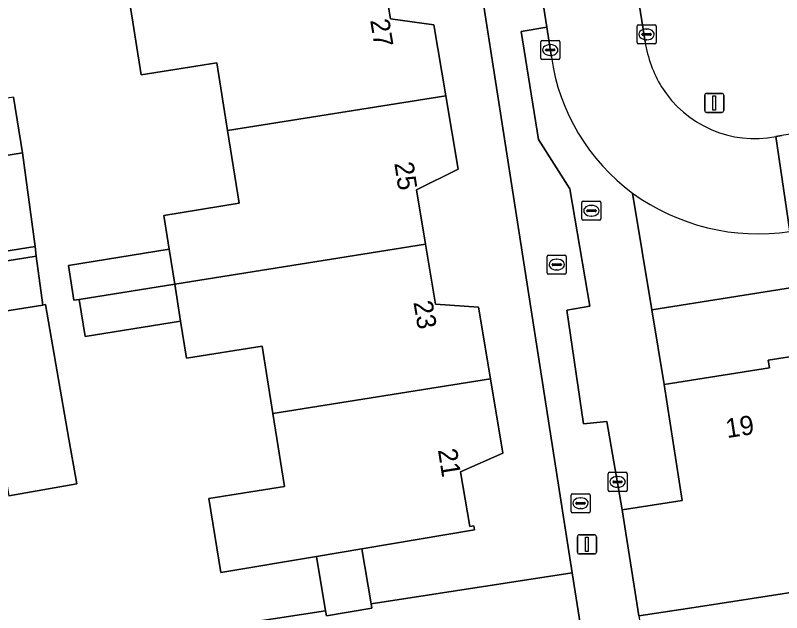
# Model space of a CAD drawing. Extents: x 160077 to 160948, y 386481 to 387498.
# Drawn here: x 160504.27 to 160544.36, y 387057.29 to 387088.51 of the extents above; entities that cross this region are included whole.
import ezdxf

# ---------------------------------------------------------------- set-up
doc = ezdxf.new("R2010")
doc.units = 0
for name, color, linetype in [('IMGEO_Brandkraan', 7, 'Continuous'), ('IMGEO_Erf', 7, 'Continuous'), ('IMGEO_Kolk', 7, 'Continuous'), ('IMGEO_Lichtmast', 7, 'Continuous'), ('IMGEO_Pand', 7, 'Continuous'), ('IMGEO_Pand_nummerreeks', 7, 'Continuous'), ('IMGEO_Rijbaan_lokaal_open', 7, 'Continuous'), ('IMGEO_Rioolput', 7, 'Continuous'), ('IMGEO_Voetpad_open', 7, 'Continuous')]:
    doc.layers.add(name, color=color, linetype=linetype)

msp = doc.modelspace()

# ---------------------------------------------------------------- linework, layer by layer
at = {"layer": 'IMGEO_Brandkraan'}
for p, q in [((160532.165, 387075.985), (160533.017, 387075.985)), ((160532.09, 387075.059), (160532.09, 387075.911)), ((160532.578, 387075.765), (160532.603, 387075.765)), ((160533.091, 387075.911), (160533.091, 387075.059)), ((160532.349, 387075.479), (160532.349, 387075.491)), ((160532.787, 387075.442), (160532.389, 387075.442)), ((160532.392, 387075.528), (160532.79, 387075.528)), ((160532.601, 387075.205), (160532.576, 387075.205)), ((160532.833, 387075.491), (160532.833, 387075.479)), ((160533.017, 387074.985), (160532.165, 387074.985))]:
    msp.add_line(p, q, dxfattribs=at)
for points in [[(160532.165, 387075.985), (160533.017, 387075.985)], [(160532.09, 387075.059), (160532.09, 387075.911)], [(160533.091, 387075.911), (160533.091, 387075.059)], [(160533.017, 387074.985), (160532.165, 387074.985)]]:
    msp.add_lwpolyline(points, dxfattribs=at)
for centre, radius, start, end in [((160532.167, 387075.909), 0.0765, 91.552, 178.448), ((160532.167, 387075.909), 0.0765, 91.552, 178.448), ((160533.015, 387075.909), 0.0765, 1.552, 88.448), ((160533.015, 387075.909), 0.0765, 1.552, 88.448), ((160532.389, 387075.488), 0.0403, 85.8775, 175.7526), ((160532.386, 387075.478), 0.0366, 178.938, 274.7102), ((160532.79, 387075.485), 0.043, 264.8664, 352.4533), ((160532.794, 387075.49), 0.0386, 1.7309, 96.639), ((160532.167, 387075.061), 0.0765, 181.552, 268.448), ((160532.167, 387075.061), 0.0765, 181.552, 268.448), ((160533.015, 387075.061), 0.0765, 271.552, 358.448), ((160533.015, 387075.061), 0.0765, 271.552, 358.448)]:
    msp.add_arc(centre, radius, start, end, dxfattribs=at)
for centre, major_axis, ratio, start_param, end_param in [((160532.577, 387075.485), (-0.387, 0.002), 0.722429, 4.712389, 7.853982), ((160532.602, 387075.485), (-0.39, 0.002), 0.717154, 1.570796, 4.712389)]:
    msp.add_ellipse(centre, major_axis=major_axis, ratio=ratio, start_param=start_param, end_param=end_param, dxfattribs=at)
at = {"layer": 'IMGEO_Erf'}
for points in [[(160523.386, 387091.347), (160523.894, 387088.324), (160526.165, 387088.024), (160526.789, 387084.31), (160527.434, 387080.472), (160525.253, 387079.396), (160525.729, 387076.56), (160526.258, 387073.412), (160528.494, 387073.265), (160529.123, 387069.522), (160529.777, 387065.633), (160527.558, 387064.656), (160528.038, 387061.796), (160528.256, 387061.832), (160528.292, 387061.615), (160522.396, 387060.624), (160522.879, 387057.753), (160533.389, 387059.367), (160524.807, 387114.481)], [(160513.761, 387056.353), (160520.499, 387057.388), (160520.022, 387060.225), (160515.019, 387059.383), (160514.4, 387063.252), (160518.349, 387063.884), (160517.738, 387067.704), (160517.175, 387071.228), (160513.228, 387070.597), (160512.92, 387072.526), (160507.922, 387071.727), (160507.612, 387073.666), (160507.338, 387073.622), (160507.047, 387075.445), (160512.318, 387076.288), (160512.035, 387078.06), (160515.984, 387078.692), (160515.377, 387082.487), (160514.81, 387086.036), (160510.863, 387085.404), (160510.248, 387089.249)], [(160624.64, 387086.938), (160537.562, 387073.116), (160538.202, 387069.219), (160543.71, 387070.083), (160543.647, 387070.489), (160545.319, 387070.751)], [(160504.177, 387084.241), (160504.641, 387081.322), (160505.303, 387076.429), (160505.37, 387075.934), (160505.717, 387073.37), (160505.847, 387073.391), (160507.076, 387066.352), (160507.483, 387064.019), (160503.937, 387063.399)], [(160547.186, 387058.717), (160540.007, 387057.603), (160536.884, 387057.118), (160537.023, 387056.231), (160538.348, 387047.784), (160601.152, 387057.778)]]:
    msp.add_lwpolyline(points, dxfattribs=at)
at = {"layer": 'IMGEO_Kolk'}
for p, q in [((160536.864, 387088.02), (160537.716, 387088.02)), ((160536.789, 387087.094), (160536.789, 387087.946)), ((160537.277, 387087.8), (160537.302, 387087.8)), ((160537.79, 387087.946), (160537.79, 387087.094)), ((160537.048, 387087.514), (160537.048, 387087.526)), ((160537.486, 387087.477), (160537.088, 387087.477)), ((160537.091, 387087.563), (160537.489, 387087.563)), ((160537.3, 387087.24), (160537.275, 387087.24)), ((160537.532, 387087.526), (160537.532, 387087.514)), ((160531.752, 387086.276), (160531.752, 387087.128)), ((160531.827, 387087.202), (160532.679, 387087.202)), ((160532.24, 387086.982), (160532.265, 387086.982)), ((160532.753, 387087.128), (160532.753, 387086.276)), ((160537.716, 387087.02), (160536.864, 387087.02)), ((160532.011, 387086.696), (160532.011, 387086.708)), ((160532.449, 387086.659), (160532.051, 387086.659)), ((160532.054, 387086.745), (160532.452, 387086.745)), ((160532.263, 387086.422), (160532.238, 387086.422)), ((160532.495, 387086.708), (160532.495, 387086.696)), ((160532.679, 387086.202), (160531.827, 387086.202)), ((160535.273, 387063.701), (160535.273, 387064.553)), ((160535.348, 387064.627), (160536.2, 387064.627)), ((160535.761, 387064.407), (160535.786, 387064.407)), ((160536.274, 387064.553), (160536.274, 387063.701)), ((160535.532, 387064.121), (160535.532, 387064.133)), ((160535.97, 387064.084), (160535.572, 387064.084)), ((160535.575, 387064.17), (160535.973, 387064.17)), ((160536.016, 387064.133), (160536.016, 387064.121)), ((160536.2, 387063.627), (160535.348, 387063.627)), ((160535.784, 387063.847), (160535.759, 387063.847))]:
    msp.add_line(p, q, dxfattribs=at)
for points in [[(160536.864, 387088.02), (160537.716, 387088.02)], [(160536.789, 387087.094), (160536.789, 387087.946)], [(160537.79, 387087.946), (160537.79, 387087.094)], [(160531.752, 387086.276), (160531.752, 387087.128)], [(160531.827, 387087.202), (160532.679, 387087.202)], [(160532.753, 387087.128), (160532.753, 387086.276)], [(160537.716, 387087.02), (160536.864, 387087.02)], [(160532.679, 387086.202), (160531.827, 387086.202)], [(160535.273, 387063.701), (160535.273, 387064.553)], [(160535.348, 387064.627), (160536.2, 387064.627)], [(160536.274, 387064.553), (160536.274, 387063.701)], [(160536.2, 387063.627), (160535.348, 387063.627)]]:
    msp.add_lwpolyline(points, dxfattribs=at)
for centre, radius, start, end in [((160536.866, 387087.944), 0.0765, 91.552, 178.448), ((160536.866, 387087.944), 0.0765, 91.552, 178.448), ((160537.714, 387087.944), 0.0765, 1.552, 88.448), ((160537.714, 387087.944), 0.0765, 1.552, 88.448), ((160537.088, 387087.523), 0.0403, 85.8775, 175.7526), ((160537.085, 387087.513), 0.0366, 178.938, 274.7102), ((160537.489, 387087.52), 0.043, 264.8664, 352.4533), ((160537.493, 387087.525), 0.0386, 1.7309, 96.639), ((160531.829, 387087.126), 0.0765, 91.552, 178.448), ((160531.829, 387087.126), 0.0765, 91.552, 178.448), ((160532.677, 387087.126), 0.0765, 1.552, 88.448), ((160532.677, 387087.126), 0.0765, 1.552, 88.448), ((160536.866, 387087.096), 0.0765, 181.552, 268.448), ((160536.866, 387087.096), 0.0765, 181.552, 268.448), ((160537.714, 387087.096), 0.0765, 271.552, 358.448), ((160537.714, 387087.096), 0.0765, 271.552, 358.448), ((160532.051, 387086.705), 0.0403, 85.8775, 175.7526), ((160532.048, 387086.695), 0.0366, 178.938, 274.7102), ((160532.452, 387086.702), 0.043, 264.8664, 352.4533), ((160532.456, 387086.707), 0.0386, 1.7309, 96.639), ((160531.829, 387086.278), 0.0765, 181.552, 268.448), ((160531.829, 387086.278), 0.0765, 181.552, 268.448), ((160532.677, 387086.278), 0.0765, 271.552, 358.448), ((160532.677, 387086.278), 0.0765, 271.552, 358.448), ((160535.35, 387064.551), 0.0765, 91.552, 178.448), ((160535.35, 387064.551), 0.0765, 91.552, 178.448), ((160536.198, 387064.551), 0.0765, 1.552, 88.448), ((160536.198, 387064.551), 0.0765, 1.552, 88.448), ((160535.572, 387064.13), 0.0403, 85.8775, 175.7526), ((160535.569, 387064.12), 0.0366, 178.938, 274.7102), ((160535.973, 387064.127), 0.043, 264.8664, 352.4533), ((160535.977, 387064.132), 0.0386, 1.7309, 96.639), ((160535.35, 387063.703), 0.0765, 181.552, 268.448), ((160535.35, 387063.703), 0.0765, 181.552, 268.448), ((160536.198, 387063.703), 0.0765, 271.552, 358.448), ((160536.198, 387063.703), 0.0765, 271.552, 358.448)]:
    msp.add_arc(centre, radius, start, end, dxfattribs=at)
for centre, major_axis, ratio, start_param, end_param in [((160537.276, 387087.52), (-0.387, 0.002), 0.722429, 4.712389, 7.853982), ((160537.301, 387087.52), (-0.39, 0.002), 0.717154, 1.570796, 4.712389), ((160532.239, 387086.702), (-0.387, 0.002), 0.722429, 4.712389, 7.853982), ((160532.264, 387086.702), (-0.39, 0.002), 0.717154, 1.570796, 4.712389), ((160535.76, 387064.127), (-0.387, 0.002), 0.722429, 4.712389, 7.853982), ((160535.785, 387064.127), (-0.39, 0.002), 0.717154, 1.570796, 4.712389)]:
    msp.add_ellipse(centre, major_axis=major_axis, ratio=ratio, start_param=start_param, end_param=end_param, dxfattribs=at)
at = {"layer": 'IMGEO_Lichtmast'}
for p, q in [((160540.432, 387084.437), (160541.222, 387084.437)), ((160541.222, 387084.437), (160540.432, 387084.437)), ((160540.332, 387083.537), (160540.332, 387084.337)), ((160540.332, 387084.337), (160540.332, 387083.537)), ((160541.322, 387084.337), (160541.322, 387083.537)), ((160541.322, 387083.537), (160541.322, 387084.337)), ((160541.222, 387083.437), (160540.432, 387083.437)), ((160540.432, 387083.437), (160541.222, 387083.437)), ((160533.673, 387060.458), (160533.673, 387061.258)), ((160533.673, 387061.258), (160533.673, 387060.458)), ((160533.773, 387061.358), (160534.563, 387061.358)), ((160534.563, 387061.358), (160533.773, 387061.358)), ((160534.663, 387061.258), (160534.663, 387060.458)), ((160534.663, 387060.458), (160534.663, 387061.258)), ((160534.563, 387060.358), (160533.773, 387060.358)), ((160533.773, 387060.358), (160534.563, 387060.358))]:
    msp.add_line(p, q, dxfattribs=at)
for points in [[(160540.752, 387084.312), (160540.902, 387084.312), (160540.902, 387083.562), (160540.752, 387083.562), (160540.752, 387084.312)], [(160534.093, 387061.233), (160534.243, 387061.233), (160534.243, 387060.483), (160534.093, 387060.483), (160534.093, 387061.233)]]:
    msp.add_lwpolyline(points, dxfattribs=at)
for centre, start, end in [((160540.432, 387084.337), 90, 180), ((160540.432, 387084.337), 90, 180), ((160541.222, 387084.337), 0, 90), ((160541.222, 387084.337), 360, 90), ((160540.432, 387083.537), 180, 270), ((160540.432, 387083.537), 180, 270), ((160541.222, 387083.537), 270, 0), ((160541.222, 387083.537), 270, 0), ((160533.773, 387061.258), 90, 180), ((160533.773, 387061.258), 90, 180), ((160534.563, 387061.258), 0, 90), ((160534.563, 387061.258), 360, 90), ((160533.773, 387060.458), 180, 270), ((160533.773, 387060.458), 180, 270), ((160534.563, 387060.458), 270, 0), ((160534.563, 387060.458), 270, 0)]:
    msp.add_arc(centre, 0.1, start, end, dxfattribs=at)
at = {"layer": 'IMGEO_Pand'}
for points in [[(160526.789, 387084.31), (160526.165, 387088.024), (160523.894, 387088.324), (160523.386, 387091.347), (160510.248, 387089.249), (160510.863, 387085.404), (160514.81, 387086.036), (160515.377, 387082.487)], [(160500, 387080.586), (160504.641, 387081.322), (160504.177, 387084.241), (160498.21, 387083.295), (160498.595, 387080.868), (160498.673, 387080.375)], [(160525.253, 387079.396), (160527.434, 387080.472), (160526.789, 387084.31), (160515.377, 387082.487), (160515.984, 387078.692), (160512.035, 387078.06), (160512.318, 387076.288), (160512.61, 387074.464), (160525.729, 387076.56)], [(160528.494, 387073.265), (160526.258, 387073.412), (160525.729, 387076.56), (160512.61, 387074.464), (160512.92, 387072.526), (160513.228, 387070.597), (160517.175, 387071.228), (160517.738, 387067.704), (160529.123, 387069.522)], [(160512.318, 387076.288), (160507.047, 387075.445), (160507.338, 387073.622), (160507.612, 387073.666), (160512.61, 387074.464)], [(160512.61, 387074.464), (160507.612, 387073.666), (160507.922, 387071.727), (160512.92, 387072.526)], [(160505.847, 387073.391), (160505.717, 387073.37), (160502.382, 387072.837), (160500, 387072.464), (160499.63, 387072.405), (160500.772, 387065.316), (160503.529, 387065.735), (160503.937, 387063.399), (160507.483, 387064.019), (160507.076, 387066.352)], [(160545.319, 387070.751), (160543.647, 387070.489), (160543.71, 387070.083), (160538.202, 387069.219), (160539.152, 387063.158), (160536.014, 387062.666), (160536.884, 387057.118), (160540.007, 387057.603), (160547.186, 387058.717), (160546.762, 387061.449)], [(160527.558, 387064.656), (160529.777, 387065.633), (160529.123, 387069.522), (160517.738, 387067.704), (160518.349, 387063.884), (160514.4, 387063.252), (160515.019, 387059.383), (160520.022, 387060.225), (160522.396, 387060.624), (160528.292, 387061.615), (160528.256, 387061.832), (160528.038, 387061.796)], [(160522.396, 387060.624), (160520.022, 387060.225), (160520.499, 387057.388), (160520.542, 387057.133), (160522.916, 387057.532), (160522.879, 387057.753)]]:
    msp.add_lwpolyline(points, close=True, dxfattribs=at)
at = {"layer": 'IMGEO_Rijbaan_lokaal_open'}
for points in [[(160524.318, 387136.787), (160526.43, 387124.048), (160527.09, 387119.812), (160527.668, 387116.105), (160527.923, 387114.471), (160528.364, 387111.64), (160529.664, 387103.302), (160530.562, 387097.546), (160532.066, 387087.893), (160532.31, 387086.331)], [(160537.214, 387087.127), (160532.759, 387115.209)], [(160630.749, 387096.134), (160617.421, 387094.065), (160617.383, 387094.044), (160613.925, 387093.125), (160613.306, 387093.026), (160589.61, 387089.37), (160584.446, 387088.555), (160544.358, 387082.226), (160544.051, 387082.178), (160544.782, 387077.213), (160574.18, 387081.761), (160607.245, 387087.027), (160611.413, 387087.739)], [(160544.782, 387077.213), (160544.051, 387082.178)]]:
    msp.add_lwpolyline(points, dxfattribs=at)
msp.add_lwpolyline([(160483.354, 387072.919), (160490.26, 387074.023), (160496.256, 387074.982), (160500, 387075.581), (160501.689, 387075.851), (160505.303, 387076.429), (160504.641, 387081.322), (160500, 387080.586), (160498.673, 387080.375), (160490.963, 387079.169), (160478.664, 387077.241), (160470.935, 387076.063), (160437.327, 387070.778), (160435.139, 387070.405), (160436.002, 387065.438), (160442.001, 387066.434), (160448.787, 387067.486), (160458.501, 387068.993), (160464.952, 387069.994), (160468.583, 387070.557), (160473.836, 387071.397), (160474.64, 387071.526)], close=True, dxfattribs=at)
for centre, radius, start, end in [((160543.916, 387088.24), 6.794, 189.4247, 210.7093), ((160542.894, 387087.836), 10.691, 188.0931, 233.6659), ((160542.954, 387087.833), 5.761, 212.1234, 280.9805), ((160543.131, 387088.276), 11.185, 234.0236, 278.4884)]:
    msp.add_arc(centre, radius, start, end, dxfattribs=at)
at = {"layer": 'IMGEO_Rioolput'}
for p, q in [((160533.977, 387078.801), (160534.829, 387078.801)), ((160533.902, 387077.875), (160533.902, 387078.727)), ((160534.39, 387078.581), (160534.415, 387078.581)), ((160534.903, 387078.727), (160534.903, 387077.875)), ((160534.161, 387078.295), (160534.161, 387078.307)), ((160534.599, 387078.258), (160534.201, 387078.258)), ((160534.204, 387078.344), (160534.602, 387078.344)), ((160534.413, 387078.021), (160534.388, 387078.021)), ((160534.645, 387078.307), (160534.645, 387078.295)), ((160534.829, 387077.801), (160533.977, 387077.801)), ((160533.337, 387062.584), (160533.337, 387063.436)), ((160533.412, 387063.51), (160534.264, 387063.51)), ((160533.825, 387063.29), (160533.85, 387063.29)), ((160534.338, 387063.436), (160534.338, 387062.584)), ((160533.596, 387063.004), (160533.596, 387063.016)), ((160534.034, 387062.967), (160533.636, 387062.967)), ((160533.639, 387063.053), (160534.037, 387063.053)), ((160534.08, 387063.016), (160534.08, 387063.004)), ((160534.264, 387062.51), (160533.412, 387062.51)), ((160533.848, 387062.73), (160533.823, 387062.73))]:
    msp.add_line(p, q, dxfattribs=at)
for points in [[(160533.977, 387078.801), (160534.829, 387078.801)], [(160533.902, 387077.875), (160533.902, 387078.727)], [(160534.903, 387078.727), (160534.903, 387077.875)], [(160534.829, 387077.801), (160533.977, 387077.801)], [(160533.337, 387062.584), (160533.337, 387063.436)], [(160533.412, 387063.51), (160534.264, 387063.51)], [(160534.338, 387063.436), (160534.338, 387062.584)], [(160534.264, 387062.51), (160533.412, 387062.51)]]:
    msp.add_lwpolyline(points, dxfattribs=at)
for centre, radius, start, end in [((160533.979, 387078.725), 0.0765, 91.552, 178.448), ((160533.979, 387078.725), 0.0765, 91.552, 178.448), ((160534.827, 387078.725), 0.0765, 1.552, 88.448), ((160534.827, 387078.725), 0.0765, 1.552, 88.448), ((160534.201, 387078.304), 0.0403, 85.8775, 175.7526), ((160534.198, 387078.294), 0.0366, 178.938, 274.7102), ((160534.602, 387078.301), 0.043, 264.8664, 352.4533), ((160534.606, 387078.306), 0.0386, 1.7309, 96.639), ((160533.979, 387077.877), 0.0765, 181.552, 268.448), ((160533.979, 387077.877), 0.0765, 181.552, 268.448), ((160534.827, 387077.877), 0.0765, 271.552, 358.448), ((160534.827, 387077.877), 0.0765, 271.552, 358.448), ((160533.414, 387063.434), 0.0765, 91.552, 178.448), ((160533.414, 387063.434), 0.0765, 91.552, 178.448), ((160534.262, 387063.434), 0.0765, 1.552, 88.448), ((160534.262, 387063.434), 0.0765, 1.552, 88.448), ((160533.636, 387063.013), 0.0403, 85.8775, 175.7526), ((160533.633, 387063.003), 0.0366, 178.938, 274.7102), ((160534.037, 387063.01), 0.043, 264.8664, 352.4533), ((160534.041, 387063.015), 0.0386, 1.7309, 96.639), ((160533.414, 387062.586), 0.0765, 181.552, 268.448), ((160533.414, 387062.586), 0.0765, 181.552, 268.448), ((160534.262, 387062.586), 0.0765, 271.552, 358.448), ((160534.262, 387062.586), 0.0765, 271.552, 358.448)]:
    msp.add_arc(centre, radius, start, end, dxfattribs=at)
for centre, major_axis, ratio, start_param, end_param in [((160534.389, 387078.301), (-0.387, 0.002), 0.722429, 4.712389, 7.853982), ((160534.414, 387078.301), (-0.39, 0.002), 0.717154, 1.570796, 4.712389), ((160533.824, 387063.01), (-0.387, 0.002), 0.722429, 4.712389, 7.853982), ((160533.849, 387063.01), (-0.39, 0.002), 0.717154, 1.570796, 4.712389)]:
    msp.add_ellipse(centre, major_axis=major_axis, ratio=ratio, start_param=start_param, end_param=end_param, dxfattribs=at)
at = {"layer": 'IMGEO_Voetpad_open'}
for points in [[(160529.209, 387137.267), (160531.96, 387120.174), (160532.453, 387120.252), (160532.953, 387117.144), (160532.46, 387117.066), (160532.759, 387115.209), (160537.214, 387087.127)], [(160536.884, 387057.118), (160536.014, 387062.666), (160535.215, 387067.29), (160533.996, 387067.16), (160533.124, 387073.105), (160534.313, 387073.305), (160533.281, 387079.44), (160531.641, 387082.017), (160530.729, 387087.671), (160532.066, 387087.893), (160530.562, 387097.546), (160530.068, 387097.471), (160529.17, 387103.227), (160529.664, 387103.302), (160528.364, 387111.64), (160527.87, 387111.565), (160527.429, 387114.396), (160527.923, 387114.471), (160527.668, 387116.105), (160527.174, 387116.029), (160526.596, 387119.736), (160527.09, 387119.812), (160526.43, 387124.048), (160524.318, 387136.787)], [(160521.425, 387136.208), (160524.575, 387115.974), (160524.807, 387114.481), (160533.389, 387059.367), (160533.87, 387056.399), (160536.911, 387036.475), (160536.941, 387036.474), (160538.068, 387029.818), (160538.052, 387029.808), (160542.778, 387000), (160544.462, 386989.375)], [(160532.31, 387086.331), (160532.066, 387087.893), (160530.729, 387087.671), (160531.641, 387082.017), (160533.281, 387079.44), (160534.313, 387073.305), (160533.124, 387073.105), (160533.996, 387067.16), (160535.215, 387067.29), (160536.014, 387062.666), (160539.152, 387063.158), (160538.202, 387069.219), (160537.562, 387073.116), (160536.56, 387079.224)], [(160536.56, 387079.224), (160537.562, 387073.116), (160624.64, 387086.938)], [(160544.051, 387082.178), (160544.358, 387082.226)], [(160502.382, 387072.837), (160505.717, 387073.37), (160505.37, 387075.934), (160501.767, 387075.359)], [(160533.87, 387056.399), (160533.389, 387059.367), (160522.879, 387057.753), (160522.916, 387057.532), (160520.542, 387057.133), (160520.499, 387057.388), (160513.761, 387056.353)]]:
    msp.add_lwpolyline(points, dxfattribs=at)
msp.add_lwpolyline([(160505.37, 387075.934), (160505.303, 387076.429), (160501.689, 387075.851), (160501.767, 387075.359)], close=True, dxfattribs=at)
for centre, radius, start, end in [((160543.916, 387088.24), 6.794, 189.4247, 210.7093), ((160542.894, 387087.836), 10.691, 188.0931, 233.6659), ((160542.954, 387087.833), 5.761, 212.1234, 280.9805), ((160543.131, 387088.276), 11.185, 234.0236, 278.4884)]:
    msp.add_arc(centre, radius, start, end, dxfattribs=at)

# ---------------------------------------------------------------- texts
at = {"layer": 'IMGEO_Pand_nummerreeks'}
for s, rotation, p in [('27', 279.3021, (160522.83, 387088.256)), ('25', 278.8176, (160524.093, 387080.785)), ('23', 279.8432, (160525.09, 387073.517)), ('19', 8.8236, (160541.501, 387066.412)), ('21', 279.0181, (160526.373, 387065.796))]:
    msp.add_text(s, height=1, rotation=rotation, dxfattribs=at).set_placement(p)

doc.saveas('drawing.dxf')
